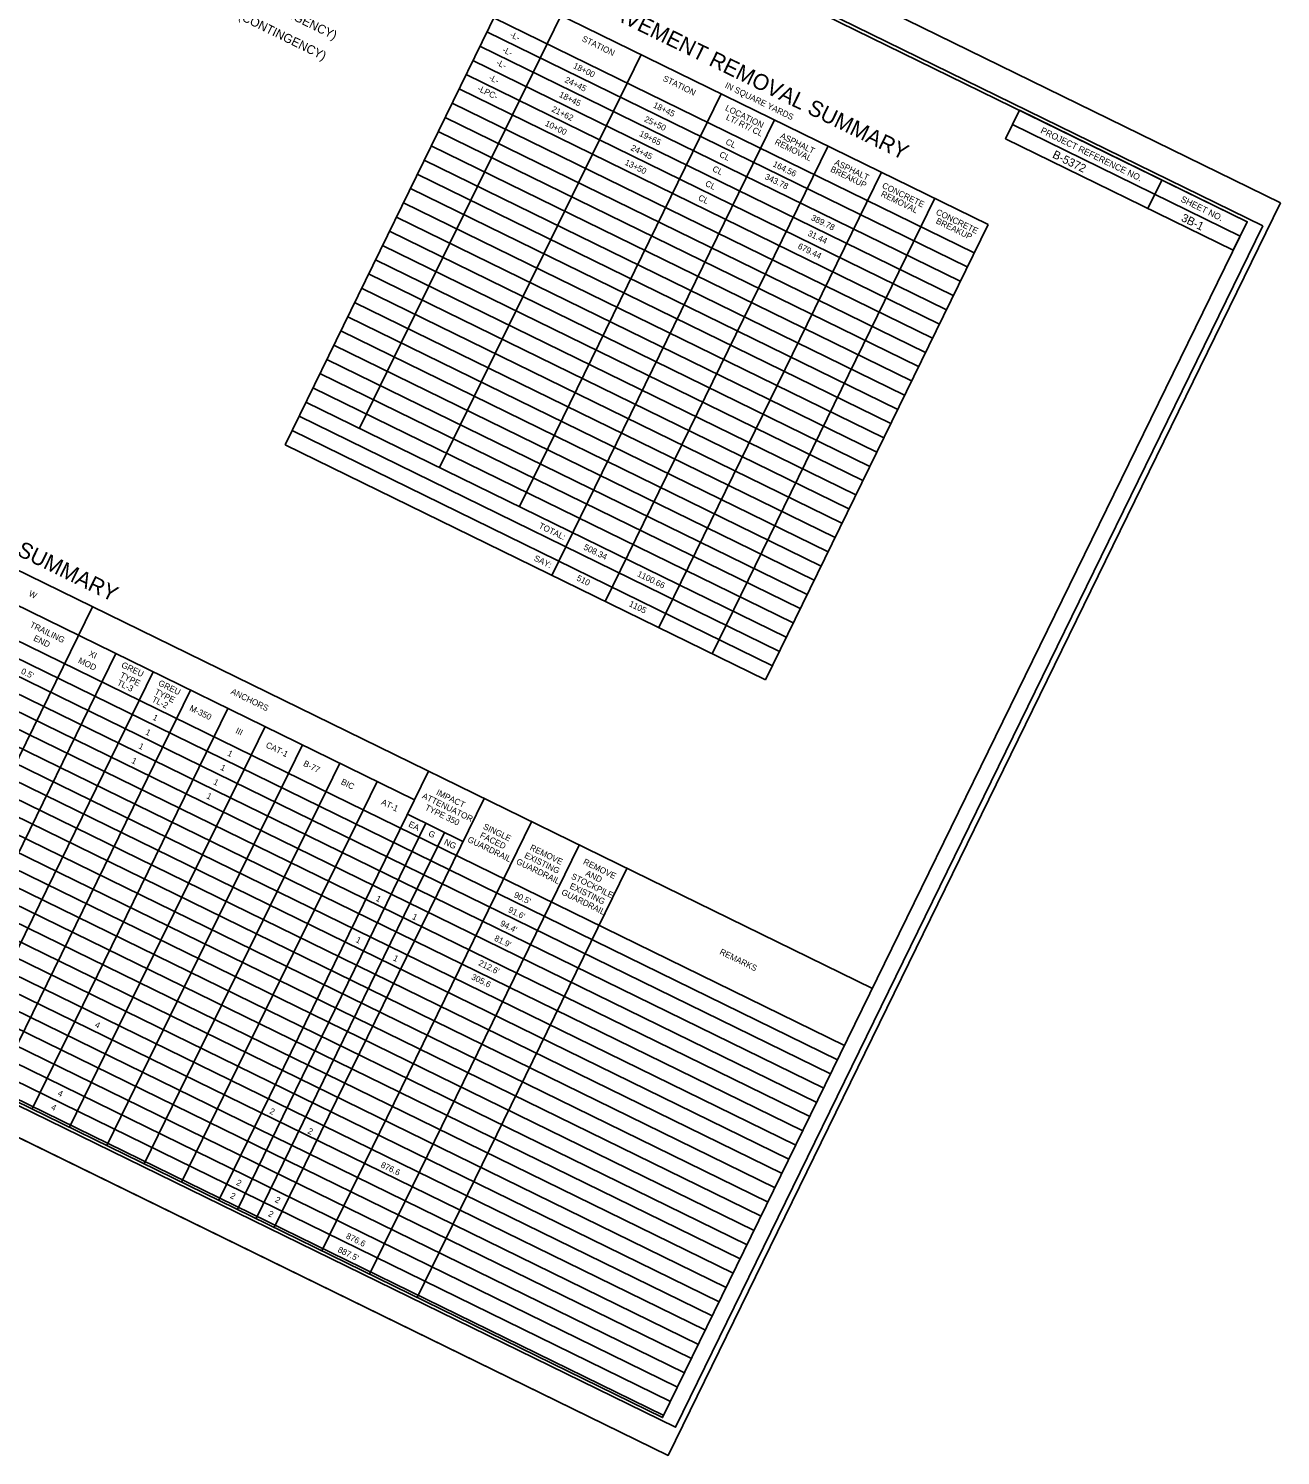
# Model space of a CAD drawing. Extents: x 1523741 to 1527628, y 632733 to 635404.
# Drawn here: x 1526640 to 1527628, y 632733 to 633859 of the extents above; entities that cross this region are included whole.
import ezdxf

# ---------------------------------------------------------------- set-up
doc = ezdxf.new("R2010")
doc.units = 0
for name, color, linetype in [('Sheet Cutting Line CELL', 7, 'Continuous'), ('Sheet Plot Border Inside CELL', 7, 'Continuous'), ('Sheet Plot Border Outside CELL', 7, 'Continuous'), ('Sheet Summary Combination CELL', 7, 'Continuous'), ('Sheet Summary Combination Grid CELL', 7, 'Continuous')]:
    doc.layers.add(name, color=color, linetype=linetype)

msp = doc.modelspace()

# ---------------------------------------------------------------- linework, layer by layer
at = {"layer": 'Sheet Cutting Line CELL'}
for p, q in [((1527628.4, 633721.4), (1526115.7, 634461.2)), ((1525632.4, 633473.1), (1527145.1, 632733.2))]:
    msp.add_line(p, q, dxfattribs=at)
at = {"layer": 'Sheet Plot Border Inside CELL'}
msp.add_lwpolyline([(1527614.5, 633703.2), (1526117.5, 634435.3), (1525653.9, 633487.5), (1527151, 632755.4)], close=True, dxfattribs=at)
at = {"layer": 'Sheet Plot Border Outside CELL'}
msp.add_lwpolyline([(1527628.4, 633721.4), (1526115.7, 634461.2), (1525632.4, 633473.1), (1527145.1, 632733.2)], close=True, dxfattribs=at)
at = {"layer": 'Sheet Summary Combination CELL'}
for p, q in [((1527145.4, 633827.7), (1527145.4, 633827.7)), ((1527151, 633824.8), (1527151, 633824.8)), ((1527159.2, 633821), (1527159.2, 633821)), ((1527164.2, 633818.5), (1527164.2, 633818.5)), ((1527416.9, 633783), (1527596.7, 633695.1)), ((1527411.4, 633771.8), (1527591.2, 633683.9)), ((1527534.8, 633739.3), (1527523.8, 633716.8))]:
    msp.add_line(p, q, dxfattribs=at)
for points in [[(1527602.2, 633706.4), (1526254.7, 634365.4), (1525793.4, 633422.2), (1527140.8, 632763.1)], [(1527422.5, 633794.3), (1527602.2, 633706.4), (1527591.2, 633683.9), (1527411.4, 633771.8)]]:
    msp.add_lwpolyline(points, close=True, dxfattribs=at)
at = {"layer": 'Sheet Summary Combination Grid CELL'}
for p, q in [((1527018.5, 633889.8), (1526842.8, 633530.4)), ((1527018.5, 633889.8), (1527397.7, 633704.3)), ((1527060.7, 633869.2), (1526901.4, 633543.5)), ((1527007.6, 633867.3), (1527386.7, 633681.9)), ((1527002.1, 633856.1), (1527381.2, 633670.7)), ((1526996.6, 633844.9), (1527375.7, 633659.4)), ((1527123.9, 633838.3), (1526964.6, 633512.6)), ((1526991.1, 633833.6), (1527370.2, 633648.2)), ((1526985.6, 633822.4), (1527364.7, 633637)), ((1526980.1, 633811.2), (1527359.2, 633625.7)), ((1526974.6, 633799.9), (1527353.7, 633614.5)), ((1527187, 633807.4), (1527027.8, 633481.7)), ((1526969.1, 633788.7), (1527348.3, 633603.3)), ((1527229.2, 633786.8), (1527053.4, 633427.4)), ((1526963.6, 633777.5), (1527342.8, 633592.1)), ((1526958.1, 633766.2), (1527337.3, 633580.8)), ((1527271.3, 633766.2), (1527095.5, 633406.8)), ((1525958.9, 633760.6), (1527306.4, 633101.5)), ((1526952.6, 633755), (1527331.8, 633569.6)), ((1526947.1, 633743.8), (1527326.3, 633558.4)), ((1527313.4, 633745.6), (1527137.7, 633386.2)), ((1526941.7, 633732.6), (1527320.8, 633547.1)), ((1526936.2, 633721.3), (1527315.3, 633535.9)), ((1527355.5, 633724.9), (1527179.8, 633365.6)), ((1525936.9, 633715.6), (1527284.4, 633056.6)), ((1526930.7, 633710.1), (1527309.8, 633524.7)), ((1525931.4, 633704.4), (1527278.9, 633045.4)), ((1526925.2, 633698.9), (1527304.3, 633513.4)), ((1527397.7, 633704.3), (1527221.9, 633345)), ((1525925.9, 633693.2), (1527273.4, 633034.2)), ((1526919.7, 633687.6), (1527298.8, 633502.2)), ((1525920.4, 633682), (1527267.9, 633022.9)), ((1526914.2, 633676.4), (1527293.3, 633491)), ((1525914.9, 633670.7), (1527262.4, 633011.7)), ((1526908.7, 633665.2), (1527287.8, 633479.8)), ((1525909.4, 633659.5), (1527256.9, 633000.5)), ((1526903.2, 633654), (1527282.3, 633468.5)), ((1525904, 633648.3), (1527251.4, 632989.2)), ((1526897.7, 633642.7), (1527276.9, 633457.3)), ((1525898.5, 633637), (1527245.9, 632978)), ((1526892.2, 633631.5), (1527271.4, 633446.1)), ((1525893, 633625.8), (1527240.4, 632966.8)), ((1526886.7, 633620.3), (1527265.9, 633434.8)), ((1525887.5, 633614.6), (1527235, 632955.6)), ((1526881.2, 633609), (1527260.4, 633423.6)), ((1525882, 633603.4), (1527229.5, 632944.3)), ((1526875.8, 633597.8), (1527254.9, 633412.4)), ((1525876.5, 633592.1), (1527224, 632933.1)), ((1526870.3, 633586.6), (1527249.4, 633401.2)), ((1525871, 633580.9), (1527218.5, 632921.9)), ((1526864.8, 633575.4), (1527243.9, 633389.9)), ((1525865.5, 633569.7), (1527213, 632910.6)), ((1526859.3, 633564.1), (1527238.4, 633378.7)), ((1525860, 633558.4), (1527207.5, 632899.4)), ((1526853.8, 633552.9), (1527232.9, 633367.5)), ((1525854.5, 633547.2), (1527202, 632888.2)), ((1526848.3, 633541.7), (1527227.4, 633356.2)), ((1525849, 633536), (1527196.5, 632877)), ((1526842.8, 633530.4), (1527221.9, 633345)), ((1525843.5, 633524.7), (1527191, 632865.7)), ((1525838.1, 633513.5), (1527185.5, 632854.5)), ((1525832.6, 633502.3), (1527180, 632843.3)), ((1525832.6, 633502.3), (1527180, 632843.3)), ((1525827.1, 633491.1), (1527174.5, 632832)), ((1525821.6, 633479.8), (1527169.1, 632820.8)), ((1525816.1, 633468.6), (1527163.6, 632809.6)), ((1526945, 633250.4), (1526516.3, 633460.1)), ((1525810.6, 633457.4), (1527158.1, 632798.4)), ((1525805.1, 633446.1), (1527152.6, 632787.1)), ((1525805.1, 633446.1), (1527152.6, 632787.1)), ((1525799.6, 633434.9), (1527147.1, 632775.9)), ((1525794.1, 633423.7), (1527141.6, 632764.7)), ((1526690.7, 633402.6), (1526525.2, 633064.2)), ((1526709.2, 633365.8), (1526554.7, 633049.8)), ((1526738.6, 633351.4), (1526584.1, 633035.4)), ((1526768.1, 633336.9), (1526613.6, 633021)), ((1526797.6, 633322.5), (1526643.1, 633006.6)), ((1526827.1, 633308.1), (1526672.6, 632992.2)), ((1526856.5, 633293.7), (1526702, 632977.8)), ((1526886, 633279.3), (1526731.5, 632963.3)), ((1526956, 633272.9), (1526790.5, 632934.5)), ((1526915.5, 633264.9), (1526761, 632948.9)), ((1526999.8, 633251.4), (1526834.3, 632913)), ((1526939.4, 633239), (1526983, 633217.6)), ((1526954, 633231.9), (1526805.2, 632927.3)), ((1526968.7, 633224.7), (1526819.9, 632920.1)), ((1527037.4, 633233.1), (1526871.9, 632894.7)), ((1527074.9, 633214.7), (1526909.4, 632876.3)), ((1527112.5, 633196.3), (1526947, 632857.9))]:
    msp.add_line(p, q, dxfattribs=at)

# ---------------------------------------------------------------- texts
at = {"layer": 'Sheet Summary Combination CELL'}
for s, height, rotation, p in [('GEOTEXTILE FOR SOIL STABILIZATION = 700 SY (CONTINGENCY)', 7, 333.9377, (1526615.5, 633979.8)), ('CLASS IV SUBGRADE STABILIZATION = 200 TON (CONTINGENCY)', 7, 333.9377, (1526607.5, 633963.4)), ('PAVEMENT REMOVAL SUMMARY', 12.5, 333.9497, (1527089.7, 633872.6)), ('-L-', 4.8, 333.9377, (1527019.8, 633852.4)), ('-L-', 4.8, 333.9377, (1527013.9, 633840.4)), ('STATION', 4.8, 333.9377, (1527076.6, 633849.1)), ('-L-', 4.8, 333.9377, (1527009, 633830.4)), ('18+00', 4.8, 333.9377, (1527069.7, 633827.8)), ('-L-', 4.8, 333.9377, (1527003.2, 633818.5)), ('24+45', 4.8, 333.9377, (1527063, 633816.7)), ('STATION', 4.8, 333.9377, (1527140.5, 633817.8)), ('-LPC-', 4.8, 333.9377, (1526994.2, 633809.9)), ('18+45', 4.8, 333.9377, (1527058.6, 633805.1)), ('IN SQUARE YARDS', 4.8, 333.9377, (1527189.5, 633812.4)), ('21+62', 4.8, 333.9377, (1527052.7, 633793.6)), ('18+45', 4.8, 333.9377, (1527132.8, 633796.8)), ('LOCATION', 4.8, 333.9377, (1527189.7, 633794.5)), ('10+00', 4.8, 333.9377, (1527047.5, 633782.4)), ('25+50', 4.8, 333.9377, (1527125.8, 633785.7)), ('LT/ RT/ CL', 4.8, 333.9377, (1527190.3, 633787.2)), ('19+65', 4.8, 333.9377, (1527121.9, 633774.3)), ('ASPHALT', 4.8, 333.9377, (1527233.1, 633772.6)), ('PROJECT REFERENCE NO.', 5, 333.9377, (1527438.6, 633776.7)), ('24+45', 4.8, 333.9377, (1527115.1, 633763.1)), ('CL', 4.8, 333.9377, (1527190, 633767.8)), ('REMOVAL', 4.8, 333.9377, (1527228.8, 633767.7)), ('13+50', 4.8, 333.9377, (1527110.4, 633751.6)), ('CL', 4.8, 333.9377, (1527185.1, 633757.8)), ('164.56', 4.8, 333.9377, (1527227.3, 633750.3)), ('ASPHALT', 4.8, 333.9377, (1527275.9, 633751.6)), ('B-5372', 6.48, 333.9377, (1527447.9, 633757.2)), ('CL', 4.8, 333.9377, (1527179.6, 633746.5)), ('343.78', 4.8, 333.9377, (1527220.9, 633740.3)), ('BREAKUP', 4.8, 333.9377, (1527272.7, 633746.2)), ('CL', 4.8, 333.9377, (1527173.9, 633734.9)), ('REMOVAL', 4.8, 333.9377, (1527312.6, 633726.7)), ('CONCRETE', 4.8, 333.9377, (1527313.5, 633733.3)), ('CL', 4.8, 333.9377, (1527168.4, 633723.7)), ('SHEET NO.', 5, 333.9377, (1527549.2, 633722.5)), ('389.78', 4.8, 333.9377, (1527257.5, 633707.9)), ('BREAKUP', 4.8, 333.9377, (1527356, 633705.4)), ('CONCRETE', 4.8, 333.9377, (1527356, 633712.4)), ('3B-1', 6.48, 333.9377, (1527549.5, 633707.3)), ('31.44', 4.8, 333.9377, (1527254.8, 633695.7)), ('679.44', 4.8, 333.9377, (1527247, 633685.5)), ('GUARDRAIL SUMMARY', 12.5, 333.9377, (1526538.5, 633488.6)), ('TOTAL:', 4.8, 333.9377, (1527042.5, 633465)), ('508.34', 4.8, 333.9377, (1527077.9, 633448.1)), ('SAY:', 4.8, 333.9377, (1527038.7, 633439.4)), ('510', 4.8, 333.9377, (1527072.4, 633423.7)), ('1100.66', 4.8, 333.9377, (1527120.3, 633427)), ('W', 4.8, 333.9377, (1526640, 633411.5)), ('1105', 4.8, 333.9377, (1527113.7, 633403.4)), ('TRAILING', 4.8, 333.9377, (1526640.9, 633386.9)), ('END', 4.8, 333.9377, (1526643.7, 633376.3)), ('MOD', 4.8, 333.9377, (1526679, 633358.7)), ('XI', 4.8, 333.9377, (1526687.4, 633364.1)), ('GREU', 4.8, 333.9377, (1526713.1, 633355.2)), ("0.5'", 4.8, 333.9377, (1526633.9, 633350.2)), ('TYPE', 4.8, 333.9377, (1526712, 633347.1)), ('TL-3', 4.8, 333.9377, (1526709.7, 633341.2)), ('TYPE', 4.8, 333.9377, (1526739.4, 633334)), ('GREU', 4.8, 333.9377, (1526742.2, 633340.9)), ('ANCHORS', 4.8, 333.9377, (1526799.5, 633334.2)), ('TL-2', 4.8, 333.9377, (1526737.2, 633328)), ('M-350', 4.8, 333.9377, (1526766.9, 633321.1)), ('1', 4.8, 333.9377, (1526737.8, 633313.8)), ('1', 4.8, 333.9377, (1526732.1, 633302.2)), ('III', 4.8, 333.9377, (1526803.2, 633303.3)), ('1', 4.8, 333.9377, (1526726.7, 633291.2)), ('CAT-1', 4.8, 333.9377, (1526827.1, 633292)), ('1', 4.8, 333.9377, (1526721.1, 633279.7)), ('1', 4.8, 333.9377, (1526796.8, 633285.5)), ('B-77', 4.8, 333.9377, (1526856.7, 633277.4)), ('1', 4.8, 333.9377, (1526791.3, 633274.4)), ('1', 4.8, 333.9377, (1526785.7, 633262.9)), ('BIC', 4.8, 333.9377, (1526886.4, 633263)), ('IMPACT', 4.8, 333.9377, (1526961.6, 633254.6)), ('1', 4.8, 333.9377, (1526780.3, 633251.9)), ('AT-1', 4.8, 333.9377, (1526918.2, 633247)), ('ATTENUATOR', 4.8, 333.9377, (1526950.5, 633251.9)), ('TYPE 350', 4.8, 333.9377, (1526952.7, 633242.7)), ('EA', 4.8, 333.9377, (1526939.7, 633229.5)), ('G', 4.8, 333.9377, (1526955.4, 633222.2)), ('FACED', 4.8, 333.9377, (1526996.1, 633220.8)), ('SINGLE', 4.8, 333.9377, (1526998.6, 633227.7)), ('NG', 4.8, 333.9377, (1526967.8, 633215.5)), ('GUARDRAIL', 4.8, 333.9377, (1526986.3, 633217.5)), ('REMOVE', 4.8, 333.9377, (1527035.5, 633211.1)), ('GUARDRAIL', 4.8, 333.9377, (1527024.7, 633200.1)), ('EXISTING', 4.8, 333.9377, (1527031.2, 633205)), ('REMOVE', 4.8, 333.9377, (1527077.6, 633199.9)), ('STOCKPILE', 4.8, 333.9377, (1527068.1, 633188.4)), ('AND', 4.8, 333.9377, (1527079.4, 633190.9)), ("90.5'", 4.8, 333.9377, (1527022.9, 633173.8)), ('GUARDRAIL', 4.8, 333.9377, (1527060.4, 633175.9)), ('EXISTING', 4.8, 333.9377, (1527066.9, 633180.8)), ('1', 4.8, 333.9377, (1526913.9, 633171)), ('1', 4.8, 333.9377, (1526942.6, 633156.6)), ("94.4'", 4.8, 333.9377, (1527012.1, 633151.3)), ("91.6'", 4.8, 333.9377, (1527018.4, 633162)), ('1', 4.8, 333.9377, (1526898.1, 633138.4)), ("81.9'", 4.8, 333.9377, (1527007.4, 633139.6)), ('REMARKS', 4.8, 333.9377, (1527185.3, 633128.9)), ('1', 4.8, 333.9377, (1526927.6, 633124)), ("212.6'", 4.8, 333.9377, (1526994.9, 633120.1)), ('305.6', 4.8, 333.9377, (1526989.3, 633109.1)), ('4', 4.8, 333.9377, (1526692.2, 633071.4)), ('4', 4.8, 333.9377, (1526662.8, 633017.4)), ('4', 4.8, 333.9377, (1526657.6, 633006.4)), ('2', 4.8, 333.9377, (1526830, 633003.2)), ('2', 4.8, 333.9377, (1526860.1, 632987.6)), ('876.6', 4.8, 333.9377, (1526917.8, 632960.8)), ('2', 4.8, 333.9377, (1526803.8, 632946.9)), ('2', 4.8, 333.9377, (1526799, 632936.6)), ('2', 4.8, 333.9377, (1526834.4, 632933.4)), ('2', 4.8, 333.9377, (1526829, 632922.3)), ('876.6', 4.8, 333.9377, (1526890.4, 632904.7)), ("887.5'", 4.8, 333.9377, (1526883.9, 632893.9))]:
    msp.add_text(s, height=height, rotation=rotation, dxfattribs=at).set_placement(p)

doc.saveas('drawing.dxf')
